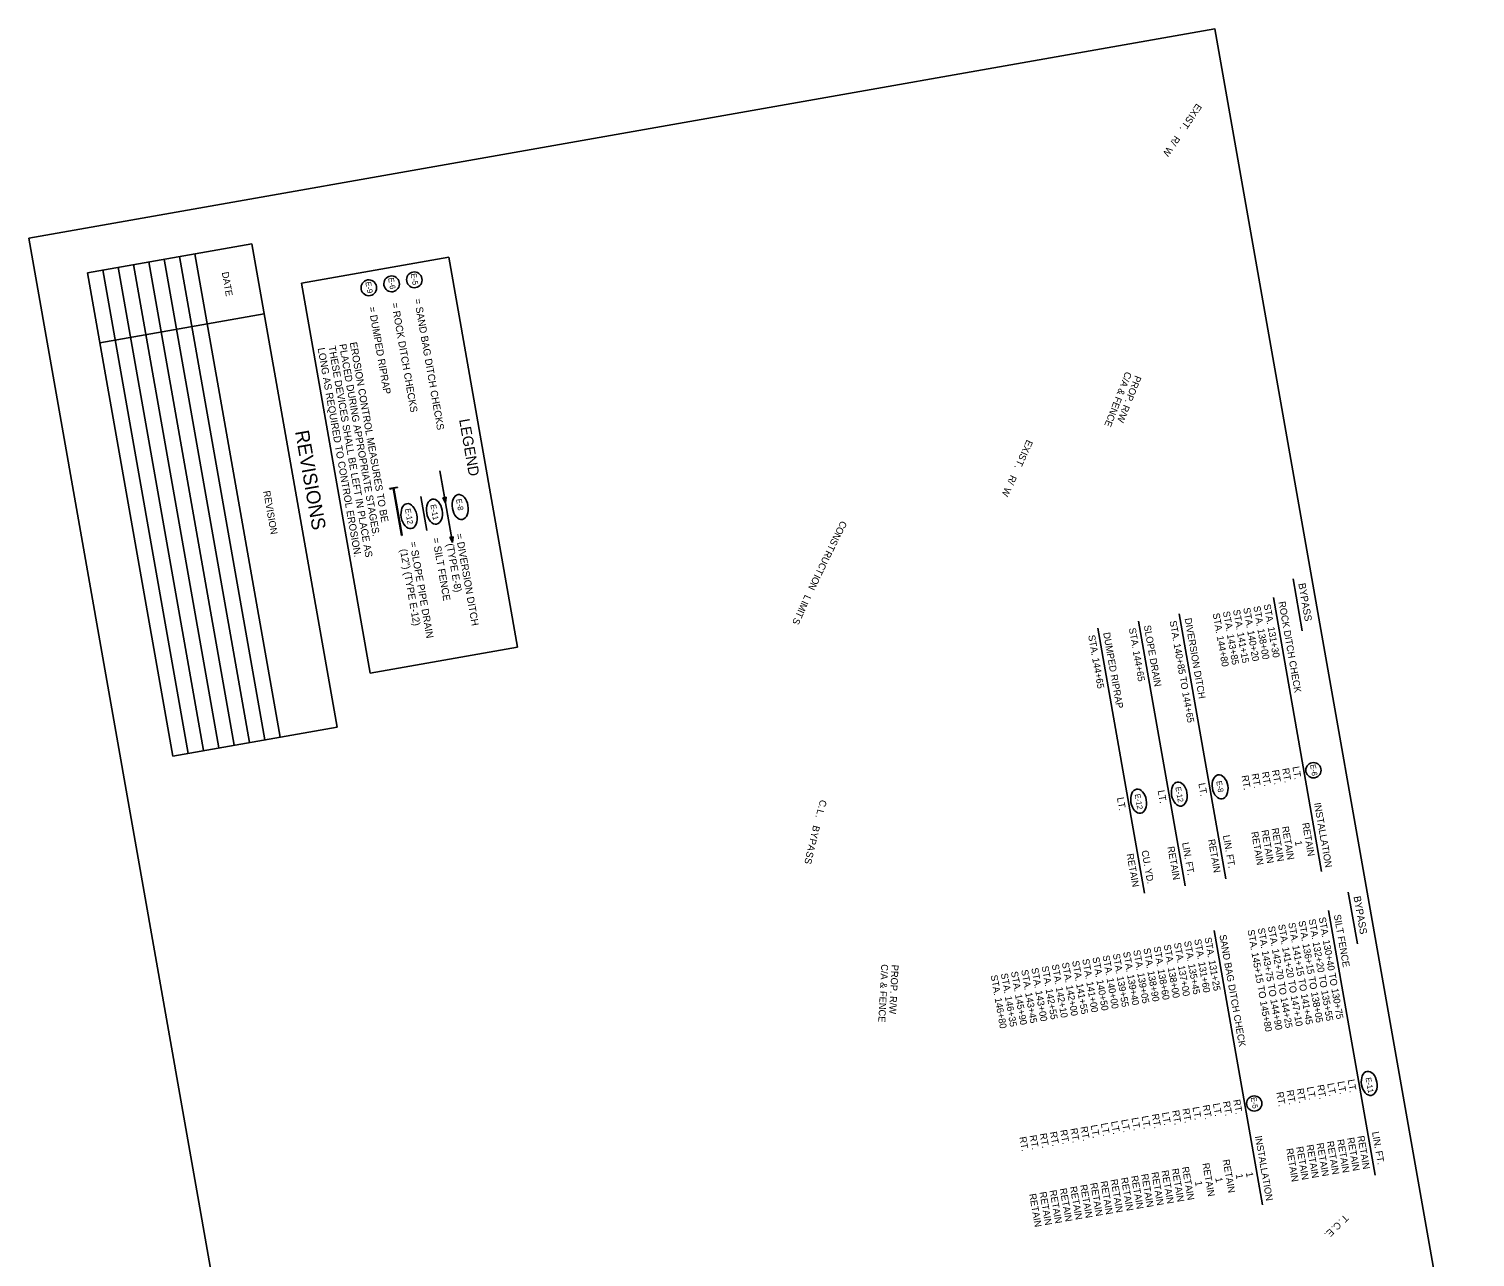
# Model space of a CAD drawing. Extents: x 979945 to 981206, y 1838799 to 1840551.
# Drawn here: x 979945 to 981196, y 1839488 to 1840551 of the extents above; entities that cross this region are included whole.
import ezdxf

# ---------------------------------------------------------------- set-up
doc = ezdxf.new("R2010")
doc.units = 0
for name, color, linetype in [('1', 7, 'Continuous'), ('44', 7, 'Continuous'), ('Default', 7, 'Continuous'), ('G-Border-Sheet', 7, 'Continuous'), ('Level 1', 7, 'Continuous'), ('Level 44', 7, 'Continuous'), ('R_Draft', 7, 'Continuous')]:
    doc.layers.add(name, color=color, linetype=linetype)

msp = doc.modelspace()

# ---------------------------------------------------------------- linework, layer by layer
at = {"layer": '1'}
for p, q in [((980300.1, 1840168.4), (980310.8, 1840108)), ((980305.6, 1840145.6), (980302.8, 1840145.1)), ((980302.8, 1840145.1), (980305, 1840140.6)), ((980303.1, 1840145.2), (980304.5, 1840141.8)), ((980303.5, 1840145.2), (980304.6, 1840141.9)), ((980303.8, 1840145.3), (980304.7, 1840141.9)), ((980304.9, 1840141.9), (980304.6, 1840145.4)), ((980305, 1840141.9), (980304.9, 1840145.5)), ((980305, 1840140.6), (980305.6, 1840145.6)), ((980305.1, 1840141.9), (980305.3, 1840145.5)), ((980311.7, 1840111.3), (980308.8, 1840110.8)), ((980311, 1840107.6), (980310.6, 1840111.1)), ((980311, 1840107.6), (980311, 1840111.2)), ((980311.1, 1840107.6), (980311.3, 1840111.3)), ((980311.1, 1840106.3), (980311.7, 1840111.3)), ((980308.8, 1840110.8), (980311.1, 1840106.3)), ((980309.2, 1840110.9), (980310.6, 1840107.5)), ((980309.5, 1840110.9), (980310.7, 1840107.6)), ((980309.9, 1840111), (980310.8, 1840107.6))]:
    msp.add_line(p, q, dxfattribs=at)
for points in [[(980300.1, 1840168.4), (980305, 1840141)], [(980306.2, 1840134.1), (980310.8, 1840108)]]:
    msp.add_lwpolyline(points, dxfattribs=at)
for centre in [(981056.3, 1839909.1), (981005.1, 1839620.6)]:
    msp.add_circle(centre, 6.61, dxfattribs=at)
for centre, major_axis, ratio in [((980273.5, 1840129.1), (1.9, -10.8), 0.622952), ((980317.8, 1840137), (1.9, -10.8), 0.622952), ((980940.2, 1839888.5), (1.8, -10.4), 0.638788), ((980975.5, 1839894.7), (1.8, -10.4), 0.638788), ((980905, 1839882.3), (1.8, -10.4), 0.638788), ((981104.6, 1839638), (1.8, -10.4), 0.638788)]:
    msp.add_ellipse(centre, major_axis=major_axis, ratio=ratio, dxfattribs=at)
at = {"layer": '44'}
for p, q in [((980256.7, 1840153.1), (980263.4, 1840154.3)), ((980256.7, 1840153.1), (980256.8, 1840152.6)), ((980256.8, 1840152.6), (980259.9, 1840153.2)), ((980267.1, 1840112.4), (980259.9, 1840153.2)), ((980260.4, 1840153.2), (980263.5, 1840153.8)), ((980267.6, 1840112.5), (980260.4, 1840153.2)), ((980263.4, 1840154.3), (980263.5, 1840153.8)), ((980267.6, 1840112.5), (980267.1, 1840112.4)), ((981038.7, 1840074.7), (981046.6, 1840029.8)), ((981021.6, 1840058.8), (981063.4, 1839821.5)), ((980905, 1840038.3), (980945.4, 1839809)), ((980940.2, 1840044.5), (980980.6, 1839815.2)), ((980869.7, 1840032.1), (980910.1, 1839802.8)), ((981086.5, 1839803.7), (981094.4, 1839758.8)), ((981069.4, 1839787.8), (981109.8, 1839558.6)), ((980970.4, 1839770.4), (981012.2, 1839533))]:
    msp.add_line(p, q, dxfattribs=at)
at = {"layer": 'Default'}
msp.add_lwpolyline([(979944.5, 1840369.9), (980971, 1840550.9), (981196.2, 1839273.6), (981147.4, 1839265), (981177.1, 1839096.8), (981031.8, 1839071.2), (981054, 1838945.6), (980221.5, 1838798.8)], close=True, dxfattribs=at)
msp.add_lwpolyline([(979944.5, 1840369.9), (980971, 1840550.9), (981196.2, 1839273.6), (981147.4, 1839265), (981177.1, 1839096.8), (981031.8, 1839071.2), (981054, 1838945.6), (980221.5, 1838798.8)], close=True, dxfattribs=at)
at = {"layer": 'G-Border-Sheet'}
for p, q in [((980180.3, 1840330.8), (980308, 1840353.3)), ((980308, 1840353.3), (980367.5, 1840015.8)), ((980180.3, 1840330.8), (980239.8, 1839993.3)), ((980239.8, 1839993.3), (980367.5, 1840015.8))]:
    msp.add_line(p, q, dxfattribs=at)
at = {"layer": 'Level 1'}
for centre, major_axis, ratio in [((980258.4, 1840330.2), (-1.19, 6.78), 0.97521), ((980278.1, 1840333.7), (-1.19, 6.78), 0.97521), ((980238.7, 1840326.8), (-1.19, 6.78), 0.97521), ((980295.5, 1840133), (1.9, -10.8), 0.622952)]:
    msp.add_ellipse(centre, major_axis=major_axis, ratio=ratio, dxfattribs=at)
at = {"layer": 'Level 44'}
msp.add_lwpolyline([(980283.7, 1840146.2), (980288.9, 1840116.6)], dxfattribs=at)
at = {"layer": 'R_Draft'}
for p, q in [((980137.5, 1840365), (979995.2, 1840339.9)), ((980137.5, 1840365), (980211.3, 1839946.5)), ((980048.3, 1840349.3), (980122.1, 1839930.8)), ((980048.3, 1840349.3), (980122.1, 1839930.8)), ((980061.6, 1840351.7), (980135.4, 1839933.1)), ((980074.9, 1840354), (980148.7, 1839935.5)), ((980088.2, 1840356.3), (980162, 1839937.8)), ((979995.2, 1840339.9), (980069, 1839921.4)), ((980008.4, 1840342.3), (980082.2, 1839923.7)), ((980021.7, 1840344.6), (980095.5, 1839926.1)), ((980035, 1840347), (980108.8, 1839928.4)), ((980148.2, 1840304.2), (980005.9, 1840279.1)), ((980211.3, 1839946.5), (980069, 1839921.4))]:
    msp.add_line(p, q, dxfattribs=at)

# ---------------------------------------------------------------- texts
at = {"layer": '1'}
for s, height, p in [('E-8 ', 4.88, (980314.2, 1840143.7)), ('E-12', 4.88, (980270, 1840135.3)), ('E-6 ', 4.8, (981053.4, 1839913.8)), ('E-8', 4.8, (980972.2, 1839899.5)), ('E-12', 4.8, (980901.6, 1839888.2)), ('E-12', 4.8, (980936.8, 1839894.4)), ('E-11', 4.8, (981101.4, 1839642.7)), ('E-5 ', 4.8, (981002.1, 1839625.7))]:
    msp.add_text(s, height=height, rotation=280, dxfattribs=at).set_placement(p)
at = {"layer": '44'}
for s, height, p in [('BYPASS', 6.25, (981043.2, 1840070.6)), ('STA. 140+20', 6, (980995.5, 1840049.4)), ('STA. 138+00', 6, (981004.3, 1840050.9)), ('STA. 131+30', 6, (981013.2, 1840052.5)), ('ROCK DITCH CHECK', 6, (981026.1, 1840054.8)), ('STA. 140+85 TO 144+65', 6, (980931.8, 1840038.1)), ('DIVERSION DITCH ', 6, (980944.8, 1840040.4)), ('STA. 144+80', 6, (980969.1, 1840044.7)), ('STA. 143+85', 6, (980977.9, 1840046.3)), ('STA. 141+15', 6, (980986.7, 1840047.8)), ('STA. 144+65', 6, (980861.3, 1840025.7)), ('DUMPED RIPRAP', 6, (980874.3, 1840028)), ('STA. 144+65', 6, (980896.5, 1840031.9)), ('SLOPE DRAIN', 6, (980909.5, 1840034.2)), ('RT.', 6, (981029.2, 1839910.5)), ('LT.', 6, (981038.1, 1839912)), ('RT.', 6, (980994, 1839904.3)), ('RT.', 6, (981002.8, 1839905.9)), ('RT.', 6, (981011.6, 1839907.4)), ('RT.', 6, (981020.4, 1839909)), ('LT.', 6, (980921.5, 1839891.4)), ('LT.', 6, (980956.7, 1839897.6)), ('LT.', 6, (980886.2, 1839885.2)), ('INSTALLATION', 6, (981056.8, 1839880.6)), ('RETAIN', 6, (981046.5, 1839863.2)), ('RETAIN', 6, (980965.1, 1839848.9)), ('LIN. FT.', 6, (980977.9, 1839852.5)), ('RETAIN', 6, (981002.4, 1839855.5)), ('RETAIN', 6, (981011.3, 1839857)), ('RETAIN', 6, (981020.1, 1839858.6)), ('RETAIN', 6, (981028.9, 1839860.1)), ('RETAIN', 6, (980894.6, 1839836.5)), ('CU. YD.', 6, (980907.5, 1839839.3)), ('RETAIN', 6, (980929.9, 1839842.7)), ('LIN. FT.', 6, (980942.6, 1839846.2)), ('1', 6, (981040.2, 1839847.6)), ('BYPASS', 6.25, (981091, 1839799.6)), ('STA. 142+70 TO 144+25', 6, (981016.9, 1839773.7)), ('STA. 141+20 TO 147+10', 6, (981025.7, 1839775.3)), ('STA. 141+15 TO 141+45', 6, (981034.5, 1839776.8)), ('STA. 136+15 TO 138+05', 6, (981043.3, 1839778.4)), ('STA. 132+20 TO 135+55', 6, (981052.1, 1839779.9)), ('STA. 130+40 TO 130+75', 6, (981060.9, 1839781.5)), ('SILT FENCE      ', 6, (981073.9, 1839783.8)), ('STA. 135+45', 6, (980944.3, 1839760.9)), ('STA. 131+60', 6, (980953.1, 1839762.5)), ('STA. 131+25', 6, (980962, 1839764)), ('SAND BAG DITCH CHECK', 6, (980974.9, 1839766.3)), ('STA. 145+15 TO 145+80', 6, (980999.2, 1839770.6)), ('STA. 143+75 TO 144+90', 6, (981008.1, 1839772.1)), ('STA. 140+00', 6, (980873.8, 1839748.5)), ('STA. 139+55', 6, (980882.6, 1839750)), ('STA. 139+40', 6, (980891.5, 1839751.6)), ('STA. 139+05', 6, (980900.3, 1839753.1)), ('STA. 138+90', 6, (980909.1, 1839754.7)), ('STA. 138+60', 6, (980917.9, 1839756.2)), ('STA. 138+00', 6, (980926.7, 1839757.8)), ('STA. 137+00', 6, (980935.5, 1839759.4)), ('STA. 143+45', 6, (980803.3, 1839736)), ('STA. 143+00', 6, (980812.1, 1839737.6)), ('STA. 142+55', 6, (980821, 1839739.2)), ('STA. 142+10', 6, (980829.8, 1839740.7)), ('STA. 142+00', 6, (980838.6, 1839742.3)), ('STA. 141+55', 6, (980847.4, 1839743.8)), ('STA. 141+00', 6, (980856.2, 1839745.4)), ('STA. 140+50', 6, (980865, 1839746.9)), ('STA. 146+80', 6, (980776.9, 1839731.4)), ('STA. 146+35', 6, (980785.7, 1839732.9)), ('STA. 145+90', 6, (980794.5, 1839734.5)), ('RT.', 6, (981059.4, 1839636.4)), ('LT.', 6, (981068.2, 1839637.8)), ('LT.', 6, (981077.1, 1839639.4)), ('LT.', 6, (981085.9, 1839641)), ('RT.', 6, (980986.9, 1839623.6)), ('RT.', 6, (981024.2, 1839630.2)), ('RT.', 6, (981033, 1839631.8)), ('RT.', 6, (981041.8, 1839633.3)), ('LT.', 6, (981050.6, 1839634.7)), ('RT.', 6, (980916.4, 1839611.2)), ('LT.', 6, (980925.2, 1839612.6)), ('RT.', 6, (980934, 1839614.3)), ('RT.', 6, (980942.8, 1839615.9)), ('LT.', 6, (980951.6, 1839617.3)), ('RT.', 6, (980960.4, 1839619)), ('LT.', 6, (980969.3, 1839620.4)), ('RT.', 6, (980978, 1839622.1)), ('RT.', 6, (980845.9, 1839598.8)), ('RT.', 6, (980854.7, 1839600.3)), ('LT.', 6, (980863.5, 1839601.7)), ('LT.', 6, (980872.3, 1839603.3)), ('LT.', 6, (980881.1, 1839604.9)), ('LT.', 6, (980889.9, 1839606.4)), ('LT.', 6, (980898.8, 1839608)), ('LT.', 6, (980907.6, 1839609.5)), ('RT.', 6, (980801.7, 1839591.4)), ('RT.', 6, (980810.6, 1839592.8)), ('RT.', 6, (980819.4, 1839594.4)), ('RT.', 6, (980828.2, 1839595.8)), ('RT.', 6, (980837, 1839597.4)), ('INSTALLATION', 6, (981005.6, 1839592.1)), ('RETAIN', 6, (981059, 1839586)), ('RETAIN', 6, (981067.8, 1839587.6)), ('RETAIN', 6, (981076.7, 1839589.1)), ('RETAIN', 6, (981085.5, 1839590.7)), ('RETAIN', 6, (981094.3, 1839592.2)), ('LIN. FT.', 6, (981107, 1839595.8)), ('RETAIN', 6, (981032.6, 1839581.3)), ('RETAIN', 6, (981041.4, 1839582.9)), ('RETAIN', 6, (981050.2, 1839584.5)), ('RETAIN', 6, (980916, 1839560.8)), ('RETAIN', 6, (980924.8, 1839562.3)), ('RETAIN', 6, (980933.6, 1839563.9)), ('RETAIN', 6, (980942.4, 1839565.4)), ('RETAIN', 6, (980960.1, 1839568.6)), ('RETAIN', 6, (980977.7, 1839571.7)), ('1', 6, (980997.8, 1839560.7)), ('RETAIN', 6, (980845.5, 1839548.4)), ('RETAIN', 6, (980854.3, 1839549.9)), ('RETAIN', 6, (980863.1, 1839551.5)), ('RETAIN', 6, (980871.9, 1839553)), ('RETAIN', 6, (980880.7, 1839554.6)), ('RETAIN', 6, (980889.6, 1839556.1)), ('RETAIN', 6, (980898.4, 1839557.7)), ('RETAIN', 6, (980907.2, 1839559.2)), ('1', 6, (980953.7, 1839553)), ('1', 6, (980971.3, 1839556.1)), ('1', 6, (980989, 1839559.2)), ('RETAIN', 6, (980810.2, 1839542.1)), ('RETAIN', 6, (980819.1, 1839543.7)), ('RETAIN', 6, (980827.9, 1839545.2)), ('RETAIN', 6, (980836.7, 1839546.8))]:
    msp.add_text(s, height=height, rotation=280, dxfattribs=at).set_placement(p)
at = {"layer": 'Level 1'}
for s, height, p in [('E-5 ', 4.88, (980275, 1840338.9)), ('E-9 ', 4.88, (980235.7, 1840331.7)), ('E-6 ', 4.88, (980255.4, 1840335.2)), ('= ROCK DITCH CHECKS', 6.25, (980258.2, 1840313.4)), ('= SAND BAG DITCH CHECKS', 6.25, (980277.9, 1840316.9)), ('= DUMPED RIPRAP', 6.25, (980238.4, 1840309.9)), ('LONG AS REQUIRED TO CONTROL EROSION.', 6.25, (980194.4, 1840274.4)), ('THESE DEVICES SHALL BE LEFT IN PLACE AS ', 6.25, (980203.7, 1840276)), ('PLACED DURING APPROPRIATE STAGES. ', 6.25, (980212.9, 1840277.7)), ('EROSION CONTROL MEASURES TO BE', 6.25, (980222.2, 1840279.3)), ('E-11 ', 4.88, (980292, 1840138.9)), ('= DIVERSION DITCH', 6.25, (980313.8, 1840113.5)), ('  (12") (TYPE E-12)', 6.25, (980264.8, 1840104.8)), ('= SLOPE PIPE DRAIN', 6.25, (980274, 1840106.4)), ('= SILT FENCE', 6.25, (980293.7, 1840109.9)), ('   (TYPE E-8)', 6.25, (980304.6, 1840111.8))]:
    msp.add_text(s, height=height, rotation=280, dxfattribs=at).set_placement(p)
at = {"layer": 'Level 44'}
msp.add_text('LEGEND', height=9.14, rotation=280, dxfattribs=at).set_placement((980316.8, 1840212.6))
at = {"layer": 'R_Draft'}
for s, height, rotation, p in [('S', 6, 235.8612, (980947.9, 1840476)), ('I', 6, 235.8612, (980949, 1840477.6)), ('X', 6, 235.8612, (980952.2, 1840482.4)), ('E', 6, 235.8612, (980955.2, 1840486.8)), ('.', 6, 235.8612, (980941.4, 1840466.4)), ('T', 6, 235.8612, (980944.7, 1840471.3)), ('/', 6, 235.8612, (980933.2, 1840454.3)), ('R', 6, 235.8612, (980936.4, 1840459)), ('W', 6, 235.8612, (980929.9, 1840449.5)), ('DATE', 6, 280, (980111.4, 1840340.1)), ('C/A & FENCE', 6, 248.4526, (980893.7, 1840254.7)), ('PROP. R/W', 6, 248.4526, (980902, 1840251.4)), ('REVISIONS', 12, 280, (980174.8, 1840202.4)), ('X', 6, 245.3622, (980806.1, 1840190.8)), ('E', 6, 245.3622, (980808.3, 1840195.7)), ('T', 6, 245.3622, (980800.5, 1840178.6)), ('S', 6, 245.3622, (980802.9, 1840183.8)), ('I', 6, 245.3622, (980803.7, 1840185.6)), ('R', 6, 245.3622, (980794.3, 1840165.2)), ('.', 6, 245.3622, (980798.1, 1840173.3)), ('REVISION', 6, 280, (980147.3, 1840150.6)), ('W', 6, 245.3622, (980789.5, 1840154.7)), ('/', 6, 245.3622, (980792, 1840160.1)), ('C', 6, 242.8604, (980647.6, 1840125.6)), ('N', 6, 243.4194, (980642.3, 1840115.3)), ('O', 6, 243.138, (980645, 1840120.6)), ('R', 6, 243.9586, (980634.7, 1840099.9)), ('T', 6, 243.9586, (980637.2, 1840105.1)), ('S', 6, 243.4194, (980639.8, 1840110.2)), ('C', 6, 244.2471, (980629.7, 1840089.5)), ('U', 6, 244.2471, (980632.2, 1840094.7)), ('O', 6, 244.6295, (980623.8, 1840077.3)), ('I', 6, 244.3173, (980624.6, 1840079.2)), ('T', 6, 244.3173, (980627.2, 1840084.4)), ('N', 6, 244.6295, (980621.3, 1840072.1)), ('M', 6, 245.6587, (980613.1, 1840054.7)), ('I', 6, 245.6587, (980613.9, 1840056.5)), ('L', 6, 244.7102, (980616.3, 1840061.5)), ('S', 6, 245.4431, (980607.2, 1840041.7)), ('T', 6, 245.4431, (980609.7, 1840047.1)), ('I', 6, 246.0976, (980610.4, 1840048.8)), ('L', 6, 255.0907, (980627.2, 1839875.7)), ('.', 6, 254.9446, (980627.9, 1839878.5)), ('C', 6, 254.6619, (980629.5, 1839884)), ('B', 6, 255.8046, (980623.5, 1839861.8)), ('.', 6, 255.3593, (980625.8, 1839870.5)), ('P', 6, 256.3748, (980620.7, 1839850.6)), ('Y', 6, 256.0873, (980622.1, 1839856.2)), ('S', 6, 256.9496, (980618, 1839839.3)), ('A', 6, 256.6575, (980619.4, 1839845.1)), ('S', 6, 257.2324, (980616.8, 1839833.8)), ('C/A & FENCE', 6, 266.993, (980682.3, 1839741.3)), ('PROP. R/W', 6, 266.993, (980691.3, 1839740.9)), ('T', 6, 224.0932, (981083.2, 1839524.9)), ('E', 6, 224.0932, (981070.7, 1839512.8)), ('.', 6, 224.0932, (981072.8, 1839514.9)), ('C', 6, 224.0932, (981076.9, 1839518.8)), ('.', 6, 224.0932, (981079, 1839520.8)), ('.', 6, 224.0932, (981066.8, 1839509.1))]:
    msp.add_text(s, height=height, rotation=rotation, dxfattribs=at).set_placement(p)

doc.saveas('drawing.dxf')
